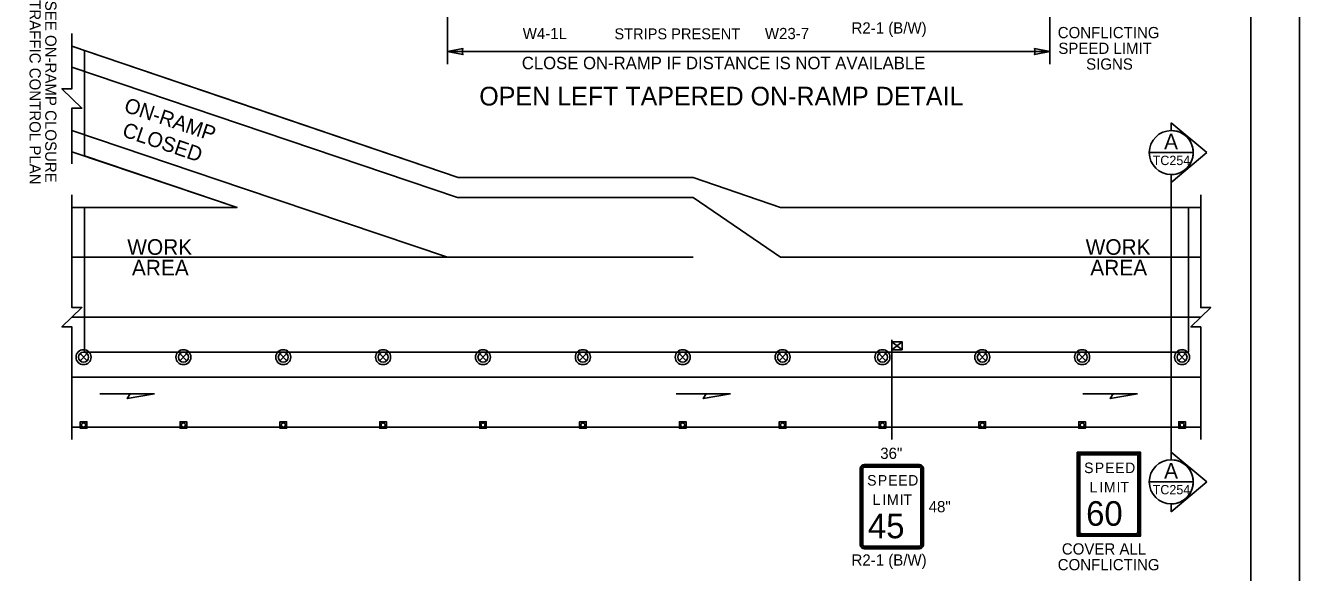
# Model space of a CAD drawing. Extents: x 99999 to 100116, y 99995 to 100013.
# Drawn here: x 100087.9 to 100096.06, y 100002.22 to 100005.72 of the extents above; entities that cross this region are included whole.
import ezdxf

# ---------------------------------------------------------------- set-up
doc = ezdxf.new("R2010")
doc.units = 0
for name, color, linetype in [('Default', 7, 'Continuous'), ('RD_MK_LineEdgeYellow', 7, 'Continuous'), ('RD_MK_LineLane', 7, 'Continuous'), ('SH_DE_DetailHeading2Text', 7, 'Continuous'), ('SH_GI_PlotLimits', 7, 'Continuous'), ('SH_GI_SheetBorder', 7, 'Continuous'), ('SH_TI_WZSectionCut', 7, 'Continuous'), ('TR_SN_ConstructionSigns', 7, 'Continuous'), ('TR_WZ_PortableSignMount5ftMinBlk-Wht', 7, 'Continuous'), ('TR_WZ_TrafficCone', 7, 'Continuous'), ('TR_WZ_TrafficSafetyDrum', 7, 'Continuous'), ('TR_WZ_WorkAreaLabel', 7, 'Continuous'), ('TR_WZ_WorkZoneDetails', 7, 'Continuous'), ('TR_WZ_WorkZoneTextCurrent', 7, 'Continuous')]:
    doc.layers.add(name, color=color, linetype=linetype)

msp = doc.modelspace()

# ---------------------------------------------------------------- linework, layer by layer
at = {"layer": 'RD_MK_LineEdgeYellow'}
for p, q in [((100088.195, 100005.4562), (100090.6655, 100004.622)), ((100088.195, 100005.0509), (100089.2943, 100004.6797)), ((100090.6655, 100004.622), (100092.1758, 100004.622)), ((100092.1758, 100004.622), (100092.7368, 100004.238)), ((100088.195, 100004.238), (100089.2533, 100004.238)), ((100092.7368, 100004.238), (100095.43, 100004.238)), ((100088.195, 100003.47), (100095.43, 100003.47))]:
    msp.add_line(p, q, dxfattribs=at)
at = {"layer": 'RD_MK_LineLane'}
for points in [[(100092.1758, 100004.238), (100090.6024, 100004.238)], [(100095.43, 100003.854), (100088.195, 100003.854)]]:
    msp.add_lwpolyline(points, dxfattribs=at)
at = {"layer": 'SH_GI_PlotLimits'}
msp.add_lwpolyline([(100079.0625, 99999.6875), (100096.0625, 99999.6875), (100096.0625, 100010.6875), (100079.0625, 100010.6875)], close=True, dxfattribs=at)
at = {"layer": 'SH_GI_SheetBorder'}
msp.add_line((100095.75, 100010.375), (100095.75, 100000), dxfattribs=at)
at = {"layer": 'SH_TI_WZSectionCut'}
for p, q in [((100095.2407, 100005.0503), (100095.2407, 100005.1002)), ((100095.2407, 100005.1002), (100095.4688, 100004.9091)), ((100095.4688, 100004.9091), (100095.2407, 100004.718)), ((100095.2407, 100004.718), (100095.2407, 100004.7679)), ((100095.2407, 100004.718), (100095.2407, 100002.99)), ((100095.2407, 100002.99), (100095.2407, 100002.94)), ((100095.4689, 100002.7988), (100095.2407, 100002.99)), ((100095.2407, 100002.6077), (100095.4689, 100002.7988)), ((100095.2407, 100002.6576), (100095.2407, 100002.6077))]:
    msp.add_line(p, q, dxfattribs=at)
for points in [[(100095.0995, 100004.9091), (100095.3819, 100004.9091)], [(100095.0995, 100002.7988), (100095.3819, 100002.7988)]]:
    msp.add_lwpolyline(points, dxfattribs=at)
for centre in [(100095.2407, 100004.9091), (100095.2407, 100002.7988)]:
    msp.add_circle(centre, 0.1412, dxfattribs=at)
for centre in [(100095.2407, 100004.9091), (100095.2407, 100002.7988)]:
    msp.add_arc(centre, 0.1412, 269.99779, 90.00221, dxfattribs=at)
at = {"layer": 'TR_SN_ConstructionSigns'}
for p, q in [((100094.638, 100002.4753), (100094.638, 100002.9646)), ((100094.638, 100002.9646), (100094.638, 100002.4753)), ((100094.6451, 100002.9646), (100094.6451, 100002.4753)), ((100094.6549, 100002.4753), (100094.6549, 100002.9646)), ((100094.6633, 100002.99), (100095.0177, 100002.99)), ((100095.0177, 100002.99), (100094.6633, 100002.99)), ((100095.0177, 100002.9829), (100094.6633, 100002.9829)), ((100094.6633, 100002.9731), (100095.0177, 100002.9731)), ((100095.0261, 100002.9646), (100095.0261, 100002.4753)), ((100095.036, 100002.4753), (100095.036, 100002.9646)), ((100095.043, 100002.9646), (100095.043, 100002.4753)), ((100095.043, 100002.4753), (100095.043, 100002.9646)), ((100093.2475, 100002.3953), (100093.2475, 100002.8846)), ((100093.2475, 100002.8846), (100093.2475, 100002.3953)), ((100093.2546, 100002.8846), (100093.2546, 100002.3953)), ((100093.2644, 100002.3953), (100093.2644, 100002.8846)), ((100093.2728, 100002.91), (100093.6272, 100002.91)), ((100093.6272, 100002.91), (100093.2728, 100002.91)), ((100093.6272, 100002.9029), (100093.2728, 100002.9029)), ((100093.2728, 100002.8931), (100093.6272, 100002.8931)), ((100093.6357, 100002.8846), (100093.6357, 100002.3953)), ((100093.6455, 100002.3953), (100093.6455, 100002.8846)), ((100093.6525, 100002.8846), (100093.6525, 100002.3953)), ((100093.6525, 100002.3953), (100093.6525, 100002.8846)), ((100095.0177, 100002.4668), (100094.6633, 100002.4668)), ((100093.6272, 100002.3868), (100093.2728, 100002.3868)), ((100093.2728, 100002.377), (100093.6272, 100002.377)), ((100094.6633, 100002.457), (100095.0177, 100002.457)), ((100095.0177, 100002.45), (100094.6633, 100002.45)), ((100094.6633, 100002.45), (100095.0177, 100002.45)), ((100093.6272, 100002.37), (100093.2728, 100002.37)), ((100093.2728, 100002.37), (100093.6272, 100002.37))]:
    msp.add_line(p, q, dxfattribs=at)
msp.add_lwpolyline([(100094.638, 100002.99), (100095.043, 100002.99), (100095.043, 100002.45), (100094.638, 100002.45)], close=True, dxfattribs=at)
for centre, radius, start, end in [((100094.6633, 100002.9646), 0.0253, 90, 180), ((100094.6633, 100002.9646), 0.0253, 90, 180), ((100094.6633, 100002.9646), 0.0183, 90, 180), ((100094.6633, 100002.9646), 0.00844, 90, 180), ((100095.0177, 100002.9646), 0.0253, 0, 90), ((100095.0177, 100002.9646), 0.0253, 360, 90), ((100095.0177, 100002.9646), 0.0183, 0, 90), ((100095.0177, 100002.9646), 0.00844, 360, 90), ((100093.2728, 100002.8846), 0.0253, 90, 180), ((100093.2728, 100002.8846), 0.0253, 90, 180), ((100093.2728, 100002.8846), 0.0183, 90, 180), ((100093.2728, 100002.8846), 0.00844, 90, 180), ((100093.6272, 100002.8846), 0.0253, 360, 90), ((100093.6272, 100002.8846), 0.0253, 360, 90), ((100093.6272, 100002.8846), 0.0183, 0, 90), ((100093.6272, 100002.8846), 0.00844, 360, 90), ((100094.6633, 100002.4753), 0.0253, 180, 270), ((100094.6633, 100002.4753), 0.0253, 180, 270), ((100094.6633, 100002.4753), 0.0183, 180, 270), ((100094.6633, 100002.4753), 0.00844, 180, 270), ((100095.0177, 100002.4753), 0.0253, 270, 0), ((100095.0177, 100002.4753), 0.0183, 270, 360), ((100095.0177, 100002.4753), 0.00844, 270, 0), ((100095.0177, 100002.4753), 0.0253, 270, 0), ((100093.2728, 100002.3953), 0.0253, 180, 270), ((100093.2728, 100002.3953), 0.0253, 180, 270), ((100093.2728, 100002.3953), 0.0183, 180, 270), ((100093.2728, 100002.3953), 0.00844, 180, 270), ((100093.6272, 100002.3953), 0.0253, 270, 360), ((100093.6272, 100002.3953), 0.0183, 270, 360), ((100093.6272, 100002.3953), 0.00844, 270, 0), ((100093.6272, 100002.3953), 0.0253, 270, 360)]:
    msp.add_arc(centre, radius, start, end, dxfattribs=at)
at = {"layer": 'TR_WZ_PortableSignMount5ftMinBlk-Wht'}
for p, q in [((100093.45, 100003.71), (100093.45, 100003.63)), ((100093.5167, 100003.644), (100093.45, 100003.696)), ((100093.5167, 100003.696), (100093.45, 100003.644)), ((100093.4834, 100003.67), (100093.4834, 100003.67)), ((100093.4835, 100003.6699), (100093.4835, 100003.6699))]:
    msp.add_line(p, q, dxfattribs=at)
msp.add_lwpolyline([(100093.5167, 100003.644), (100093.5167, 100003.696), (100093.45, 100003.696), (100093.45, 100003.644)], close=True, dxfattribs=at)
at = {"layer": 'TR_WZ_TrafficCone'}
for points in [[(100088.2481, 100003.142), (100088.2907, 100003.142), (100088.2907, 100003.1846), (100088.2481, 100003.1846), (100088.2481, 100003.142)], [(100088.2481, 100003.1846), (100088.2907, 100003.1846), (100088.2907, 100003.142), (100088.2481, 100003.142), (100088.2481, 100003.1846)], [(100088.8881, 100003.142), (100088.9307, 100003.142), (100088.9307, 100003.1846), (100088.8881, 100003.1846), (100088.8881, 100003.142)], [(100088.8881, 100003.1846), (100088.9307, 100003.1846), (100088.9307, 100003.142), (100088.8881, 100003.142), (100088.8881, 100003.1846)], [(100089.5281, 100003.142), (100089.5707, 100003.142), (100089.5707, 100003.1846), (100089.5281, 100003.1846), (100089.5281, 100003.142)], [(100089.5281, 100003.1846), (100089.5707, 100003.1846), (100089.5707, 100003.142), (100089.5281, 100003.142), (100089.5281, 100003.1846)], [(100090.1681, 100003.142), (100090.2107, 100003.142), (100090.2107, 100003.1846), (100090.1681, 100003.1846), (100090.1681, 100003.142)], [(100090.1681, 100003.1846), (100090.2107, 100003.1846), (100090.2107, 100003.142), (100090.1681, 100003.142), (100090.1681, 100003.1846)], [(100090.8081, 100003.142), (100090.8507, 100003.142), (100090.8507, 100003.1846), (100090.8081, 100003.1846), (100090.8081, 100003.142)], [(100090.8081, 100003.1846), (100090.8507, 100003.1846), (100090.8507, 100003.142), (100090.8081, 100003.142), (100090.8081, 100003.1846)], [(100091.4481, 100003.142), (100091.4907, 100003.142), (100091.4907, 100003.1846), (100091.4481, 100003.1846), (100091.4481, 100003.142)], [(100091.4481, 100003.1846), (100091.4907, 100003.1846), (100091.4907, 100003.142), (100091.4481, 100003.142), (100091.4481, 100003.1846)], [(100092.0881, 100003.142), (100092.1307, 100003.142), (100092.1307, 100003.1846), (100092.0881, 100003.1846), (100092.0881, 100003.142)], [(100092.0881, 100003.1846), (100092.1307, 100003.1846), (100092.1307, 100003.142), (100092.0881, 100003.142), (100092.0881, 100003.1846)], [(100092.7281, 100003.142), (100092.7707, 100003.142), (100092.7707, 100003.1846), (100092.7281, 100003.1846), (100092.7281, 100003.142)], [(100092.7281, 100003.1846), (100092.7707, 100003.1846), (100092.7707, 100003.142), (100092.7281, 100003.142), (100092.7281, 100003.1846)], [(100093.3681, 100003.142), (100093.4107, 100003.142), (100093.4107, 100003.1846), (100093.3681, 100003.1846), (100093.3681, 100003.142)], [(100093.3681, 100003.1846), (100093.4107, 100003.1846), (100093.4107, 100003.142), (100093.3681, 100003.142), (100093.3681, 100003.1846)], [(100094.0081, 100003.142), (100094.0507, 100003.142), (100094.0507, 100003.1846), (100094.0081, 100003.1846), (100094.0081, 100003.142)], [(100094.0081, 100003.1846), (100094.0507, 100003.1846), (100094.0507, 100003.142), (100094.0081, 100003.142), (100094.0081, 100003.1846)], [(100094.6481, 100003.142), (100094.6907, 100003.142), (100094.6907, 100003.1846), (100094.6481, 100003.1846), (100094.6481, 100003.142)], [(100094.6481, 100003.1846), (100094.6907, 100003.1846), (100094.6907, 100003.142), (100094.6481, 100003.142), (100094.6481, 100003.1846)], [(100095.2881, 100003.142), (100095.3307, 100003.142), (100095.3307, 100003.1846), (100095.2881, 100003.1846), (100095.2881, 100003.142)], [(100095.2881, 100003.1846), (100095.3307, 100003.1846), (100095.3307, 100003.142), (100095.2881, 100003.142), (100095.2881, 100003.1846)]]:
    msp.add_lwpolyline(points, dxfattribs=at)
for centre in [(100088.2694, 100003.1633), (100088.9094, 100003.1633), (100089.5494, 100003.1633), (100090.1894, 100003.1633), (100090.8294, 100003.1633), (100091.4694, 100003.1633), (100092.1094, 100003.1633), (100092.7494, 100003.1633), (100093.3894, 100003.1633), (100094.0294, 100003.1633), (100094.6694, 100003.1633), (100095.3094, 100003.1633)]:
    msp.add_circle(centre, 0.0133, dxfattribs=at)
at = {"layer": 'TR_WZ_TrafficSafetyDrum'}
for p, q in [((100088.2468, 100003.5753), (100088.292, 100003.6206)), ((100088.292, 100003.5753), (100088.2468, 100003.6206)), ((100088.8868, 100003.5753), (100088.932, 100003.6206)), ((100088.932, 100003.5753), (100088.8868, 100003.6206)), ((100089.5268, 100003.5753), (100089.572, 100003.6206)), ((100089.572, 100003.5753), (100089.5268, 100003.6206)), ((100090.1668, 100003.5753), (100090.212, 100003.6206)), ((100090.212, 100003.5753), (100090.1668, 100003.6206)), ((100090.8068, 100003.5753), (100090.852, 100003.6206)), ((100090.852, 100003.5753), (100090.8068, 100003.6206)), ((100091.4468, 100003.5753), (100091.492, 100003.6206)), ((100091.492, 100003.5753), (100091.4468, 100003.6206)), ((100092.0868, 100003.5753), (100092.132, 100003.6206)), ((100092.132, 100003.5753), (100092.0868, 100003.6206)), ((100092.7268, 100003.5753), (100092.772, 100003.6206)), ((100092.772, 100003.5753), (100092.7268, 100003.6206)), ((100093.3668, 100003.5753), (100093.412, 100003.6206)), ((100093.412, 100003.5753), (100093.3668, 100003.6206)), ((100094.0068, 100003.5753), (100094.052, 100003.6206)), ((100094.052, 100003.5753), (100094.0068, 100003.6206)), ((100094.6468, 100003.5753), (100094.692, 100003.6206)), ((100094.692, 100003.5753), (100094.6468, 100003.6206)), ((100095.2868, 100003.5753), (100095.332, 100003.6206)), ((100095.332, 100003.5753), (100095.2868, 100003.6206))]:
    msp.add_line(p, q, dxfattribs=at)
for centre, radius in [((100088.2694, 100003.598), 0.048), ((100088.2694, 100003.598), 0.048), ((100088.2694, 100003.598), 0.032), ((100088.9094, 100003.598), 0.048), ((100088.9094, 100003.598), 0.048), ((100088.9094, 100003.598), 0.032), ((100089.5494, 100003.598), 0.048), ((100089.5494, 100003.598), 0.048), ((100089.5494, 100003.598), 0.032), ((100090.1894, 100003.598), 0.048), ((100090.1894, 100003.598), 0.048), ((100090.1894, 100003.598), 0.032), ((100090.8294, 100003.598), 0.048), ((100090.8294, 100003.598), 0.048), ((100090.8294, 100003.598), 0.032), ((100091.4694, 100003.598), 0.048), ((100091.4694, 100003.598), 0.048), ((100091.4694, 100003.598), 0.032), ((100092.1094, 100003.598), 0.048), ((100092.1094, 100003.598), 0.048), ((100092.1094, 100003.598), 0.032), ((100092.7494, 100003.598), 0.048), ((100092.7494, 100003.598), 0.048), ((100092.7494, 100003.598), 0.032), ((100093.3894, 100003.598), 0.048), ((100093.3894, 100003.598), 0.048), ((100093.3894, 100003.598), 0.032), ((100094.0294, 100003.598), 0.048), ((100094.0294, 100003.598), 0.048), ((100094.0294, 100003.598), 0.032), ((100094.6694, 100003.598), 0.048), ((100094.6694, 100003.598), 0.048), ((100094.6694, 100003.598), 0.032), ((100095.3094, 100003.598), 0.048), ((100095.3094, 100003.598), 0.048), ((100095.3094, 100003.598), 0.032)]:
    msp.add_circle(centre, radius, dxfattribs=at)
at = {"layer": 'TR_WZ_WorkZoneDetails'}
for p, q in [((100090.6024, 100009.31), (100090.6024, 100005.4763)), ((100094.4628, 100007.0454), (100094.4628, 100005.4763)), ((100088.195, 100005.5914), (100090.6703, 100004.75)), ((100094.4628, 100005.5563), (100090.6024, 100005.5563)), ((100089.2533, 100004.558), (100088.195, 100004.915)), ((100090.6703, 100004.75), (100092.1758, 100004.75)), ((100092.1758, 100004.75), (100092.7368, 100004.558)), ((100090.6024, 100004.238), (100089.2943, 100004.6797)), ((100088.195, 100004.558), (100089.2533, 100004.558)), ((100092.7368, 100004.558), (100095.43, 100004.558)), ((100089.2533, 100004.238), (100090.6024, 100004.238)), ((100093.45, 100003.63), (100093.45, 100003.07)), ((100088.5676, 100003.3639), (100088.3747, 100003.3639)), ((100092.2594, 100003.3639), (100092.0665, 100003.3639)), ((100094.8672, 100003.3639), (100094.6743, 100003.3639)), ((100088.195, 100003.15), (100095.43, 100003.15))]:
    msp.add_line(p, q, dxfattribs=at)
for points in [[(100088.195, 100004.8378), (100088.195, 100005.1943), (100088.259, 100005.1943), (100088.131, 100005.3182), (100088.195, 100005.3182), (100088.195, 100005.6714)], [(100088.195, 100003.07), (100088.195, 100003.792), (100088.131, 100003.792), (100088.259, 100003.9159), (100088.195, 100003.9159), (100088.195, 100004.638)], [(100095.43, 100003.07), (100095.43, 100003.792), (100095.366, 100003.792), (100095.494, 100003.9159), (100095.43, 100003.9159), (100095.43, 100004.638)]]:
    msp.add_lwpolyline(points, dxfattribs=at)
for points in [[(100088.275, 100003.63), (100088.275, 100004.558), (100089.2533, 100004.558), (100088.275, 100004.8881), (100088.275, 100004.8881), (100088.275, 100004.8881), (100088.275, 100005.5642), (100088.275, 100005.5642), (100088.275, 100005.5642), (100089.2641, 100005.228), (100090.6703, 100004.75), (100092.1758, 100004.75), (100092.7368, 100004.558), (100095.35, 100004.558), (100095.35, 100003.63)], [(100090.6024, 100005.5563), (100090.7007, 100005.5756), (100090.6962, 100005.5563), (100090.7007, 100005.537)], [(100094.4628, 100005.5563), (100094.3645, 100005.5756), (100094.3691, 100005.5563), (100094.3645, 100005.537)], [(100088.7248, 100003.3639), (100088.5497, 100003.333), (100088.5676, 100003.3639)], [(100092.4166, 100003.3639), (100092.2415, 100003.333), (100092.2594, 100003.3639)], [(100095.0245, 100003.3639), (100094.8494, 100003.333), (100094.8672, 100003.3639)]]:
    msp.add_lwpolyline(points, close=True, dxfattribs=at)

# ---------------------------------------------------------------- texts
at = {"layer": 'Default'}
for s, p in [('S', (100093.2914, 100002.775)), ('P', (100093.3596, 100002.775)), ('E', (100093.4257, 100002.775)), ('E', (100093.4899, 100002.775)), ('D', (100093.554, 100002.775)), ('L', (100093.3265, 100002.6512)), ('I', (100093.3886, 100002.6512)), ('M', (100093.4183, 100002.6512)), ('I', (100093.4993, 100002.6512)), ('T', (100093.5229, 100002.6512))]:
    msp.add_text(s, height=0.0675, rotation=360, dxfattribs=at).set_placement(p)
msp.add_text('45', height=0.1575, dxfattribs=at).set_placement((100093.2965, 100002.4375))
at = {"layer": 'SH_DE_DetailHeading2Text'}
msp.add_text('OPEN LEFT TAPERED ON-RAMP DETAIL', height=0.12, rotation=360, dxfattribs=at).set_placement((100090.8055, 100005.211))
at = {"layer": 'SH_TI_WZSectionCut'}
for s, height, rotation, p in [('A', 0.1, 0.00995, (100095.1945, 100004.9297)), ('TC254', 0.06, 360, (100095.1214, 100004.8291)), ('A', 0.1, 0.00995, (100095.1945, 100002.8195)), ('TC254', 0.06, 360, (100095.1214, 100002.7188))]:
    msp.add_text(s, height=height, rotation=rotation, dxfattribs=at).set_placement(p)
at = {"layer": 'TR_SN_ConstructionSigns'}
for s, p in [('W4-1L', (100091.084, 100005.6363)), ('36"', (100093.3753, 100002.946))]:
    msp.add_text(s, height=0.072, rotation=360, dxfattribs=at).set_placement(p)
for s, height, p in [('W23-7', 0.072, (100092.636, 100005.6363)), ('CONFLICTING', 0.072, (100094.5128, 100005.6423)), ('SPEED LIMIT', 0.072, (100094.5168, 100005.5415)), ('SIGNS', 0.072, (100094.6947, 100005.4407)), ('S', 0.0675, (100094.6819, 100002.855)), ('P', 0.0675, (100094.7501, 100002.855)), ('E', 0.0675, (100094.8162, 100002.855)), ('E', 0.0675, (100094.8803, 100002.855)), ('D', 0.0675, (100094.9445, 100002.855)), ('L', 0.0675, (100094.717, 100002.7312)), ('I', 0.0675, (100094.7791, 100002.7312)), ('M', 0.0675, (100094.8088, 100002.7312)), ('I', 0.0675, (100094.8898, 100002.7312)), ('T', 0.0675, (100094.9134, 100002.7312)), ('60', 0.1575, (100094.6949, 100002.5175)), ('COVER ALL', 0.072, (100094.5392, 100002.333)), ('CONFLICTING', 0.072, (100094.5128, 100002.2322))]:
    msp.add_text(s, height=height, dxfattribs=at).set_placement(p)
at = {"layer": 'TR_WZ_WorkAreaLabel'}
for s, p in [('WORK', (100088.5496, 100004.254)), ('WORK', (100094.6919, 100004.254)), ('AREA', (100088.5793, 100004.1219)), ('AREA', (100094.7215, 100004.1219))]:
    msp.add_text(s, height=0.1, dxfattribs=at).set_placement(p)
at = {"layer": 'TR_WZ_WorkZoneDetails'}
for s, height, rotation, p in [('TRAFFIC CONTROL PLAN', 0.072, 270, (100087.923, 100005.8862)), ('SEE ON-RAMP CLOSURE', 0.072, 270, (100088.0238, 100005.8822)), ('ON-RAMP', 0.096, 341.34097, (100088.5223, 100005.1734)), ('CLOSED', 0.096, 341.34097, (100088.5108, 100005.0152)), ('48"', 0.072, 360, (100093.6858, 100002.604)), ('R2-1 (B/W)', 0.072, 360, (100093.1913, 100002.262))]:
    msp.add_text(s, height=height, rotation=rotation, dxfattribs=at).set_placement(p)
for s, height, p in [('R2-1 (B/W)', 0.072, (100093.1913, 100005.672)), ('STRIPS PRESENT', 0.07, (100091.6716, 100005.6353))]:
    msp.add_text(s, height=height, dxfattribs=at).set_placement(p)
at = {"layer": 'TR_WZ_WorkZoneTextCurrent'}
msp.add_text('CLOSE ON-RAMP IF DISTANCE IS NOT AVAILABLE', height=0.08, dxfattribs=at).set_placement((100091.0782, 100005.4434))

doc.saveas('drawing.dxf')
